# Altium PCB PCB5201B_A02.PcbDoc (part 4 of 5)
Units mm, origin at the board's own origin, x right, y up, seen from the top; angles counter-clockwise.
Board outline 115 x 60 mm, 6 copper layers (Top Layer, GND Layer 2, Signal Layer 3, Signal Layer 4, VCC Layer 5, Bottom Layer), stack 1.555 mm thick; 355 components, 250 nets, 1223 pads, 1070 vias.
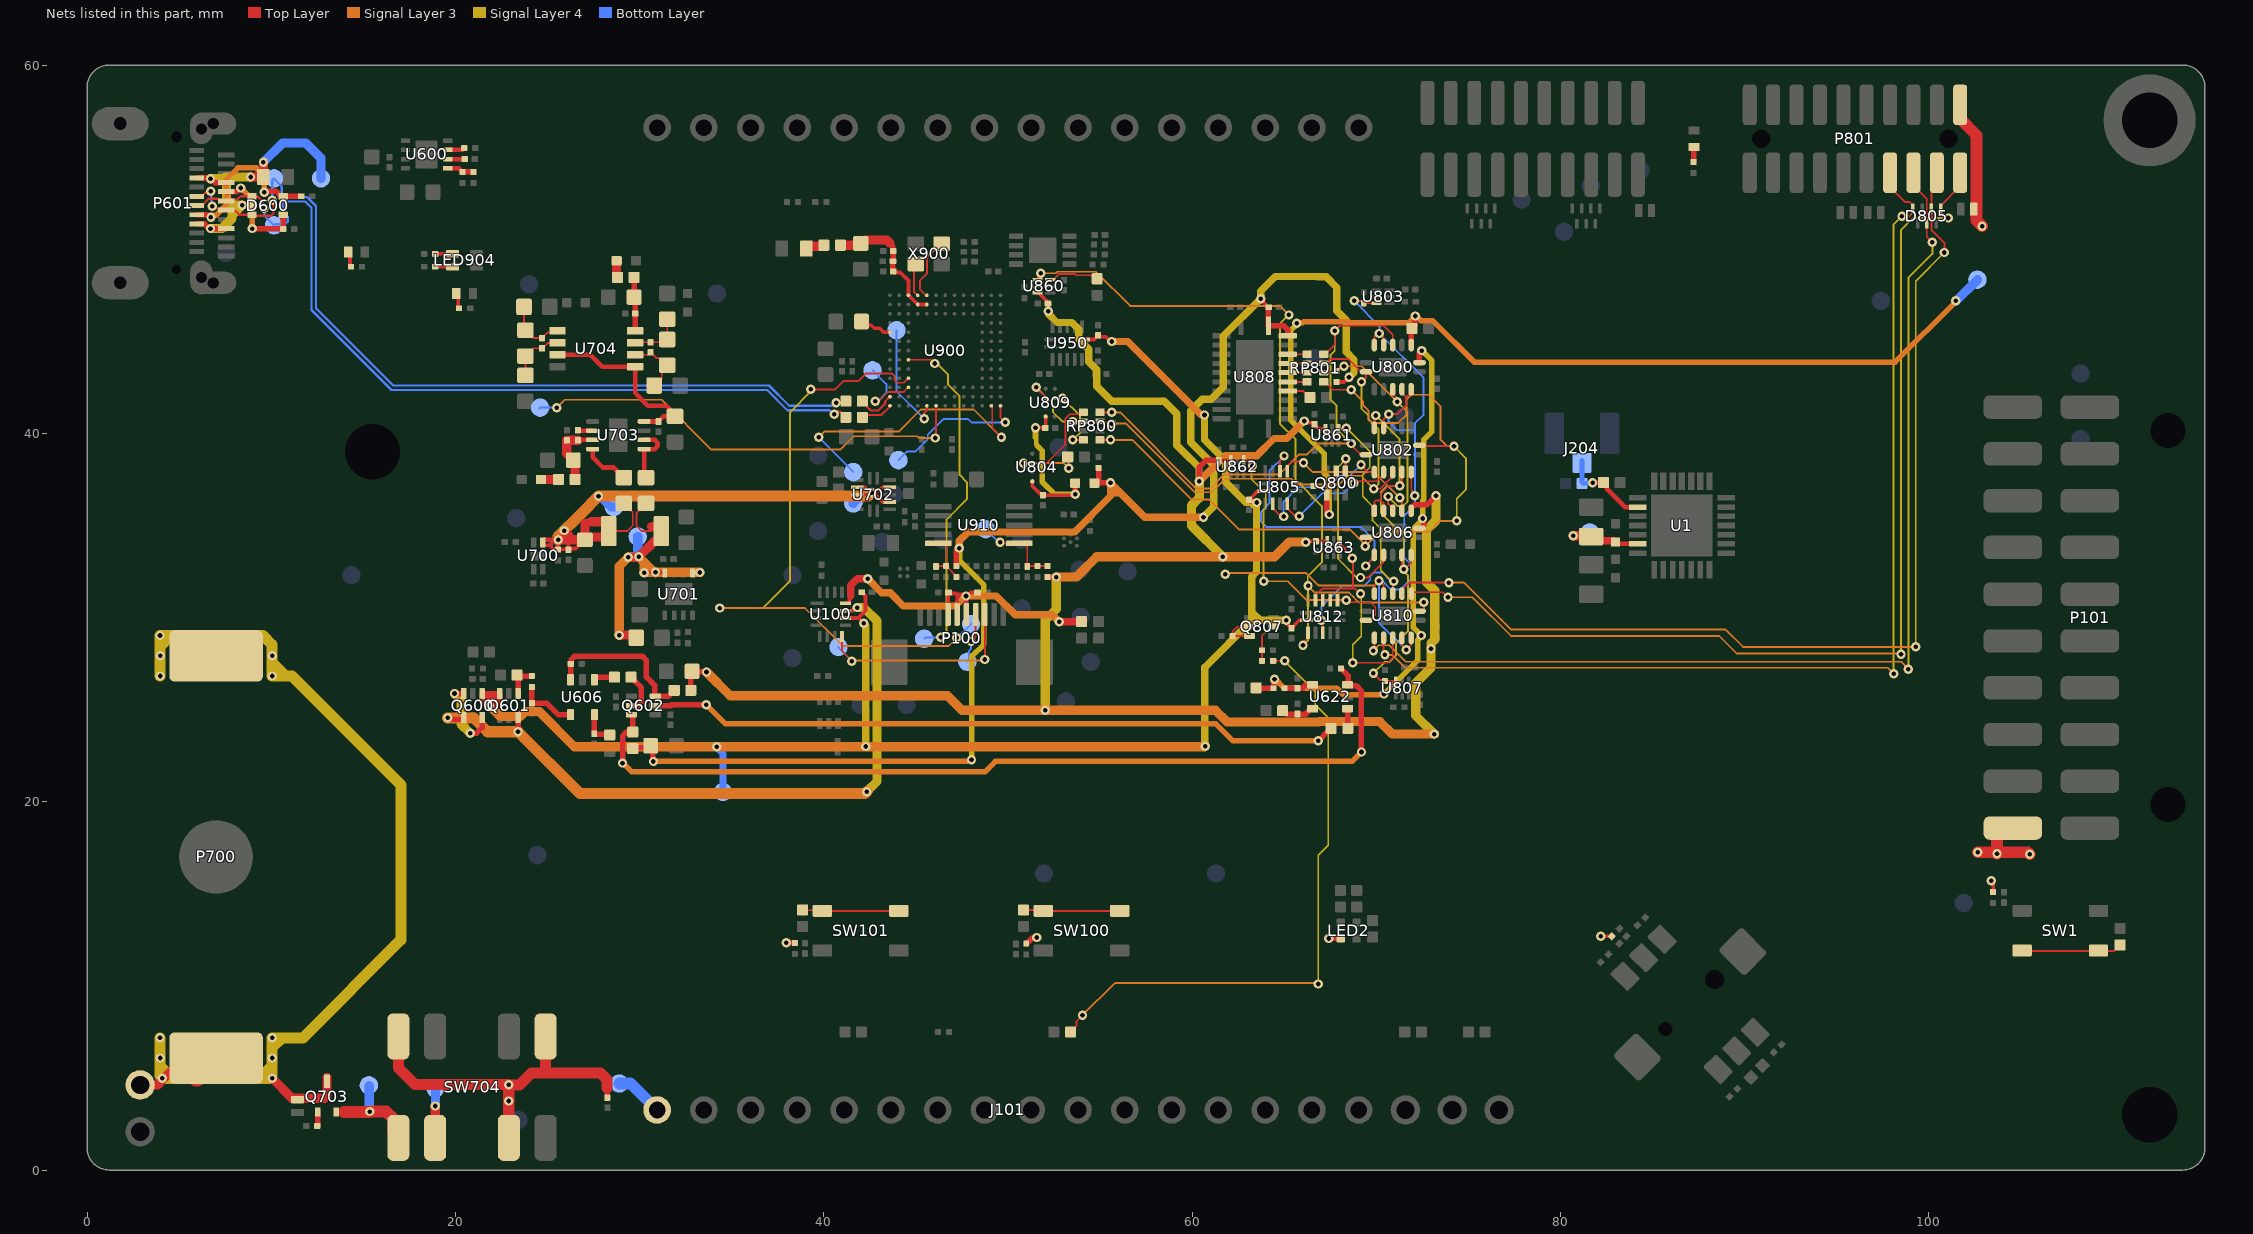
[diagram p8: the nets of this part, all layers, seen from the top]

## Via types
v1: diameter 0.508, hole 0.25, Top Layer to Bottom Layer, tented both sides, 1070 vias

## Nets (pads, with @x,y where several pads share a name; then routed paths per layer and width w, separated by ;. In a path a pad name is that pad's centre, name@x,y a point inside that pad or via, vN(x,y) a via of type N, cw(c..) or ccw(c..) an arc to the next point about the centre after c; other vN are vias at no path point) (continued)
N17208311: P100.8 TP152.1 U100.8 | length 12.3
  Top Layer w0.1: U100.8@40.99,28.975 40.99,28.21 41.531,27.669 v1(41.531,27.63) ; v1(48.75,27.725) P100.8@48.75,30.175
  Signal Layer 3 w0.1: v1(41.531,27.63) 41.576,27.675 v1@48.75,27.675
  Bottom Layer w0.1: TP152.1@40.8,28.4 40.8,28.38 41.531,27.65 v1(41.531,27.63)
N17208347: P100.7 TP153.1 | length 2.8
  Top Layer w0.1: v1(48,28.7) 48.25,28.95 P100.7@48.25,30.175
  Bottom Layer w0.1: TP153.1@47.8,27.6 47.891,27.691 47.891,28.191 48,28.3 v1(48,28.7)
N17209732: R104.1 SW100.1 SW100.2 | length 5.2
  Top Layer w0.1: R104.1@50.847,14.12 51.88,14.12 SW100.1@51.925,14.075 52.193,14.075 SW100.2@56.075,14.075
N17209791: R105.1 SW101.1 SW101.2 | length 5.4
  Top Layer w0.1: R105.1@38.8,14.175 38.865,14.11 39.89,14.11 SW101.1@39.925,14.075 ; SW101.1@39.9,14.05 SW101.1@39.925,14.075 ; SW101.2@44.075,14.075 SW101.1@39.925,14.075
N17247543: R7.2 SW1.3 SW1.4 | length 5.7
  Top Layer w0.1: SW1.3@104.848,11.9 110.075,11.9 R7.2@110.4,12.225
N17481376: D703.1 P700.1 Q703.3 ST701.2 | length 63.3
  Top Layer w0.5: ST701.2@2.875,4.62 3.82,4.62 v1@4.087,4.887 ; v1(4.087,4.981) v1@4.087,4.887 ; P700.1@7,6.078 5.278,6.078 v1@4.087,4.887 ; v1(10.046,4.981) 11.127,3.9 12.886,3.9 13.025,4.039 Q703.3@13.025,5.025
  Top Layer w1: P700.1@5.947,5.025 P700.1@7,6.078
  Signal Layer 4 w0.6: v1@3.95,27.9 v1@3.962,27.912 ; v1(3.958,7.181) 3.958,5.649 ; v1(3.962,26.825) v1@3.962,27.912 ; 3.975,5.666 3.958,5.649 ; 9.15,4.975 9.371,4.975 9.377,4.981 ; 10.05,6.65 10.581,7.181 ; 10.05,27.6 10.05,27.55 10.775,26.825 ; 3.958,5.649 4.625,4.981 ; 3.958,5.649 3.958,5.11 v1(4.087,4.981) 4.625,4.981 ; v1@3.962,27.912 v1(3.962,27.925) 3.962,28.437 ; 3.962,28.437 4.55,29.025 ; 3.962,28.437 3.962,29.019 3.958,29.023 v1(3.958,29.025) 4.55,29.025 ; 4.55,29.025 9.546,29.025 10.046,28.525 v1(10.046,27.925) v1(10.046,26.825) 10.775,26.825 ; 4.625,4.981 9.377,4.981 ; 9.377,4.981 10.046,5.65 ; 9.377,4.981 v1(10.046,4.981) 10.046,5.65 ; 10.046,5.65 v1(10.046,6.081) v1(10.046,7.181) 10.581,7.181 ; 10.581,7.181 11.714,7.181 17.039,12.506 17.039,20.919 11.133,26.825 10.775,26.825
  other v1: 3.962,6.081
N17481477: Q703.1 R792.2 | length 0.8
  Top Layer w0.3: R792.2@12.5,2.4 12.51,2.4 12.52,2.41 12.52,2.45 12.525,2.455 Q703.1@12.525,3.15
N17490696: C729.1 R718.2 U703.4 U704.3 U704.5 | length 10.5
  Top Layer w0.25: U704.3@25.545,44.275 27.325,44.275 27.975,43.625 U704.5@29.756,43.625 29.756,42.194 30.45,41.5 31.454,41.5 31.6,41.354 31.6,41.225 31.9,40.925 R718.2@31.925,40.925 31.3,40.925 C729.1@31.025,40.65 U703.4@30.25,40.65
N17490733: C766.2 R764.1 R765.2 U704.1 | length 3.4
  Top Layer w0.1: R764.1@23.725,46.875 23.725,45.675 R765.2@23.8,45.6 24.225,45.175 C766.2@24.7,45.175 24.7,45.195 24.81,45.305 24.83,45.305 25.009,45.484 25.453,45.484 U704.1@25.545,45.575
N17490783: C766.1 R765.1 R767.2 U704.2 | length 3.1
  Top Layer w0.1: R767.2@23.8,43.15 R765.1@23.8,44.2 24.225,44.625 C766.1@24.7,44.625 24.7,44.645 24.81,44.755 24.859,44.755 25.009,44.905 25.524,44.905 U704.2@25.545,44.925
N17490812: R709.1 U703.1 U703.2 | length 3.4
  Top Layer w0.25: U703.1@30.25,39.15 30.25,37.7 R709.1@30.35,37.6 R709.1@30.375,37.6 ; U703.2@30.25,39.65 30.825,39.65 30.971,39.504 30.971,39.296 30.825,39.15 U703.1@30.275,39.15
N17490814: R710.1 U703.8 | length 2.6
  Top Layer w0.25: U703.8@27.45,39.15 27.45,38.7 28,38.15 28.6,38.15 28.825,37.925 28.825,37.9 29.125,37.6 R710.1@29.15,37.6
N17490860: C710.2 U703.6 | length 0.8
  Top Layer w0.25: C710.2@26.65,40.175 26.675,40.15 U703.6@27.45,40.15
N17490888: L700.2 R717.1 | length 1
  Top Layer w0.5: L700.2@24.65,37.5 R717.1@25.6,37.5
N17491034: C770.2 R768.1 R769.2 U704.7 | length 2.7
  Top Layer w0.1: U704.7@29.756,44.925 29.781,44.95 C770.2@30.6,44.95 R769.2@31.35,44.95 ; R769.2@31.5,45.1 R768.1@31.5,46.2
N17491060: C770.1 R769.1 R771.2 U704.6 | length 3.5
  Top Layer w0.1: U704.6@29.756,44.275 30.475,44.275 C770.1@30.6,44.4 30.9,44.1 31.1,44.1 R769.1@31.5,43.7 31.2,43.4 31.2,43 R771.2@30.8,42.6
N17491108: L704.2 R731.2 | length 0.9
  Top Layer w0.5: L704.2@28.757,49.375 28.75,49.375 28.75,48.525 R731.2@28.8,48.475
N17491110: C730.1 C731.1 R731.1 U704.8 | length 2.9
  Top Layer w0.3: R731.1@29.7,48.475 C731.1@29.7,47.4 29.775,47.325 29.775,46.512 C730.1@29.772,46.509 29.764,46.501 29.764,45.583 U704.8@29.756,45.575
N17517174: RP801.5 U808.21 | length 1.1
  Top Layer w0.1: U808.21@65.195,44.3 RP801.5@66.25,44.3
N17517201: RP801.6 U808.20 | length 1.1
  Top Layer w0.1: U808.20@65.195,43.8 RP801.6@66.25,43.8
N17517230: RP801.7 U808.19 | length 1.1
  Top Layer w0.1: U808.19@65.195,43.3 RP801.7@66.25,43.3
N17517259: RP801.8 U808.18 | length 1.1
  Top Layer w0.1: U808.18@65.195,42.8 RP801.8@66.25,42.8
N17517278: R805.1 U808.17 | length 1.3
  Top Layer w0.1: U808.17@65.195,42.3 66.05,42.3 R805.1@66.4,41.95
N17517488: U802.9 U805.2 | length 7.7
  Top Layer w0.1: U805.2@64.375,36.185 64.375,35.945 v1@64.795,35.525 ; v1@69,38.3 v1(69.175,38.3) 69.575,37.9 U802.9@69.9,37.9
  Bottom Layer w0.1: v1(64.975,35.491) 64.975,36.3 65.75,37.075 67.375,37.075 68,37.7 68.575,37.7 v1(69.175,38.3)
N17517496: U802.10 U805.4 | length 6.7
  Top Layer w0.1: U805.4@65.175,36.185 65.175,35.925 65.6,35.5 v1(65.825,35.5) ; v1(68.775,37.3) 68.875,37.4 69.776,37.4 70.024,37.4 70.4,37.776 U802.10@70.4,37.9
  Bottom Layer w0.1: v1(65.825,35.5) 67.075,36.75 68.225,36.75 v1(68.775,37.3)
N17517567: R808.1 U802.6 U802.12 U806.5 U806.6 U806.12 U806.13 U807.3 | length 24.6
  Top Layer w0.1: v1(69.85,26.975) 70.224,26.601 70.424,26.601 R808.1@70.475,26.55 ; U806.6@69.9,35.8 69.9,36.275 69.975,36.35 70.25,36.35 ; U802.6@69.9,40.3 69.912,40.312 69.912,40.912 v1(69.975,40.975) ; U806.5@70.4,35.8 70.4,36.2 70.25,36.35 ; R808.1@70.475,26.525 70.5,26.55 71.038,26.55 U807.3@71.063,26.525 ; U806.12@71.4,33.4 71.4,32.835 71.5,32.735 v1(71.5,32.625) ; U802.12@71.4,37.9 71.4,37.275 v1(71.275,37.15) 70.669,37.15 70.25,36.731 70.25,36.35 ; v1@71.5,32.575 71.9,32.975 U806.13@71.9,33.4
  Signal Layer 4 w0.1: v1@69.85,27.025 69.9,27.025 70.457,27.582 70.707,27.582 71.075,27.95 71.075,28.6 71.725,29.25 71.725,32.29 71.5,32.515 v1(71.5,32.625) 71.5,34.45 70.25,35.7 70.25,36.8 70.6,37.15 v1(71.275,37.15) 71.275,39.675 v1(69.975,40.975)
N17517613: RP800.5 U804.C1 | length 4.2
  Top Layer w0.1: U804.C1@51.825,38.4 52.125,38.4 53.125,39.4 53.125,40.8 53.132,40.807 53.132,40.813 53.362,41.043 53.993,41.043 RP800.5@54.1,41.15
N17517626: RP800.6 U809.C2 | length 4.4
  Top Layer w0.1: v1(51.546,42.505) 51.546,42.464 52.05,41.96 U809.C2@52.05,41.925 ; v1(53.525,40.65) RP800.6@54.1,40.65
  Signal Layer 4 w0.1: v1(51.546,42.505) 52.45,41.601 52.45,41.15 52.95,40.65 v1(53.525,40.65)
N17517692: RP800.8 U809.C1 | length 3.8
  Top Layer w0.1: U809.C1@52.55,41.925 52.555,41.92 52.958,41.92 v1(52.964,41.914) ; v1(53.525,39.65) RP800.8@54.1,39.65
  Signal Layer 4 w0.1: v1(52.964,41.914) 53.918,40.96 53.918,40.043 v1(53.525,39.65)
N17517773: U805.9 U806.3 | length 8.1
  Top Layer w0.1: U805.9@65.175,37.955 65.175,38.25 65.4,38.475 65.975,38.475 v1(66.05,38.4) ; v1(71.275,36.5) 71.4,36.375 U806.3@71.4,35.8
  Signal Layer 3 w0.1: v1(66.05,38.4) 66.55,37.9 69.881,37.9 71.275,36.506 v1(71.275,36.5)
N17517791: U805.10 U806.9 | length 14
  Top Layer w0.1: U805.10@64.775,37.955 64.775,38.55 64.997,38.772 v1(64.997,38.778) ; v1(69.425,32.8) 69.9,33.275 U806.9@69.9,33.4
  Bottom Layer w0.1: v1(64.997,38.778) 64.997,38.772 64.2,37.975 64.2,36.2 63.75,35.75 63.75,35.2 64.025,34.925 69.15,34.925 69.9,34.175 69.9,33.275 v1(69.425,32.8)
N17517812: Q800.1 U806.10 | length 9.9
  Top Layer w0.1: Q800.1@68.325,37.95 68.334,37.959 68.334,38.609 v1(68.347,38.622) ; v1(69.15,32.175) 69.55,32.175 70.375,33 70.375,33.375 U806.10@70.4,33.4
  Signal Layer 4 w0.1: v1(68.347,38.622) 68.347,38.597 67.925,38.175 67.925,33.206 68.956,32.175 v1(69.15,32.175)
N17517960: R810.1 U804.C2 | length 3.7
  Top Layer w0.1: v1(50.85,38.388) 50.863,38.4 U804.C2@51.325,38.4 ; R810.1@53.25,38.725 53.3,38.675 v1(53.3,38.1)
  Signal Layer 3 w0.1: v1(50.85,38.388) 53.038,38.388 53.325,38.1 v1(53.3,38.1)
N17517966: Q800.2 R815.1 | length 1.7
  Top Layer w0.1: R815.1@66.59,37.142 67.192,37.142 67.825,37.775 Q800.2@67.825,37.95
N17518258: C804.1 C810.1 L801.2 U804.A2 U809.A2 | length 9.7
  Top Layer w0.2: U804.A2@51.325,37.4 51.325,37.15 51.825,36.65 C804.1@51.9,36.65 53.6,36.65 v1(53.65,36.7) ; v1(51.5,40.3) C810.1@52.025,40.3 52.05,40.325 U809.A2@52.05,40.925
  Top Layer w0.3: v1(53.65,36.7) L801.2@53.65,37.3
  Signal Layer 4 w0.25: 51.5,39.8 51.55,39.75 51.55,39.375 51.6,39.325
  Signal Layer 4 w0.3: 51.5,39.8 v1(51.5,40.3) ; 51.6,39.325 51.875,39.05 51.875,37.35 52.525,36.7 v1(53.65,36.7)
N17535327: U810.1 U812.1 U860.4 | length 42.6
  Top Layer w0.1: U860.4@51.6,48.35 U860.4@51.675,48.35 ; v1(66.025,28.5) 66.025,28.625 66.3,28.9 U812.1@66.3,29.165 ; U810.1@72.35,30.35 72.375,30.375 72.55,30.375 72.6,30.425 72.599,30.808 v1(72.582,30.825)
  Top Layer w0.2: U860.4@51.675,48.35 U860.4@51.725,48.4
  Top Layer w0.3: U860.4@51.725,48.4 51.725,48.582 51.794,48.651 v1(51.794,48.707)
  Signal Layer 3 w0.1: v1(51.794,48.707) 51.805,48.696 52.588,48.696 52.674,48.782 54.78,48.782 56.637,46.925 64.775,46.925 65.262,46.438 v1(65.262,46.434) ; v1(66.3,31.725) 66.668,31.357 68.524,31.357 68.807,31.074 68.807,31.062 69.037,30.832 69.049,30.832 69.056,30.825 v1(72.582,30.825)
  Signal Layer 4 w0.1: v1(65.262,46.434) 64.775,45.947 64.775,40.525 65.625,39.675 65.625,37.475 67.05,36.05 67.05,33 66.287,32.237 66.287,31.738 v1(66.3,31.725) 66.3,28.775 v1(66.025,28.5)
N17535335: R882.1 U860.3 | length 2.8
  Top Layer w0.1: U860.3@52.3,48.35 52.45,48.35 52.755,48.655 53.65,48.655 53.715,48.59 54.66,48.59 R882.1@54.85,48.4
N17535359: U810.4 U812.3 U861.4 | length 17.4
  Top Layer w0.1: v1(67.025,29.85) 67.1,29.775 U812.3@67.1,29.165 ; U861.4@67.95,40.25 68.425,40.25 v1@68.45,40.275 ; U810.4@70.9,31.3 70.9,31.875 70.95,31.925 v1(70.95,31.975)
  Signal Layer 4 w0.1: v1(68.375,40.275) 68.4,40.275 69.65,39.025 69.65,38.15 69.268,37.768 69.268,36.582 69.8,36.05 69.8,35.275 70.25,34.825 70.25,32.575 70.85,31.975 v1(70.95,31.975)
  Bottom Layer w0.1: v1(67.025,29.85) 67.025,30.6 68.15,31.725 69.35,31.725 69.675,32.05 69.675,32.25 69.875,32.45 70.325,32.45 70.8,31.975 v1(70.95,31.975)
N17535385: U810.8 U812.8 U862.4 | length 15.5
  Top Layer w0.1: U862.4@62.8,38.55 62.833,38.55 62.85,38.533 62.998,38.533 v1(63.283,38.248) ; U812.8@67.9,30.935 68.36,30.935 v1(68.375,30.95) 68.493,30.832 69.693,30.832 69.95,30.575 69.95,30.125 69.675,29.85 U810.8@69.45,29.85
  Signal Layer 3 w0.1: v1(63.9,31.975) 65.2,31.975 66.225,30.95 v1(68.375,30.95)
  Signal Layer 4 w0.1: v1(63.283,38.248) 63.225,38.189 63.225,37.525 64,36.75 64,35.95 63.875,35.825 v1@63.875,31.975
N17535407: U810.11 U812.11 U863.4 | length 13.2
  Top Layer w0.1: U812.11@66.7,30.935 66.7,31.2 67.075,31.575 68.743,31.575 ; U863.4@68.05,34.15 68.05,34.025 68.3,33.775 68.3,33.7 68.7,33.3 v1(68.7,33.225) 68.743,33.182 68.743,31.575 ; v1@68.723,27.55 70.625,27.55 70.9,27.825 U810.11@70.9,28.9 ; v1(69.15,31.3) 69.125,31.3 68.85,31.575 68.743,31.575
  Signal Layer 4 w0.1: v1(68.725,27.55) 68.725,28.525 69.193,28.993 69.193,31.218 69.15,31.261 v1(69.15,31.3)
N17535812: Q807.5 Q807.6 R838.1 | length 2.2
  Top Layer w0.1: Q807.6@63.125,29 63.123,28.998 62.203,28.998 R838.1@62.201,28.996 62.201,29.251 62.45,29.5 Q807.5@63.125,29.5
N17535874: Q807.2 R839.2 R841.1 | length 2.2
  Top Layer w0.1: R841.1@63.804,27.652 63.802,27.654 R839.2@63.8,28.225 R839.2@63.8,28.225 63.8,29.025 64.275,29.5 Q807.2@64.425,29.5
N17542071: R601.1 R602.2 U600.5 | length 1.5
  Top Layer w0.25: U600.5@19.582,54.397 20.182,54.397 R601.1@20.382,54.197
  Top Layer w0.3: R601.1@20.382,54.197 R602.2@20.982,54.197
N17542108: R600.1 U600.7 | length 0.9
  Top Layer w0.25: U600.7@19.582,55.397 20.382,55.397 R600.1@20.482,55.497
N17542152: C602.1 U600.6 | length 0.9
  Top Layer w0.25: U600.6@19.582,54.897 C602.1@20.507,54.897
N17542390: Q602.6 R674.1 R675.1 U606.3 | length 8.6
  Top Layer w0.3: U606.3@26.25,26.625 26.255,26.63 26.255,27.485 R674.1@26.26,27.49 26.27,27.49 26.28,27.5 26.28,27.707 26.474,27.9 30.15,27.9 30.375,27.675 30.375,26.773 30.825,26.323 Q602.6@30.825,25.8 ; Q602.6@30.85,25.725 31.557,25.725 R675.1@31.882,26.05
N17542428: Q602.2 R679.2 | length 2.2
  Top Layer w0.3: R679.2@29.535,26.761 30.1,26.196 30.1,25.426 29.899,25.225 Q602.2@29.55,25.225
N17542505: Q601.4 R628.1 R672.2 | length 1.8
  Top Layer w0.3: R628.1@23.35,26.875 R628.1@23.4,26.825 ; Q601.4@23.4,25.875 R628.1@23.4,26.825 ; R672.2@24.15,26.825 R628.1@23.4,26.825
N17542511: C621.1 R672.1 U606.4 | length 3.4
  Top Layer w0.3: R672.1@24.15,26.225 C621.1@24.15,25.35 24.95,25.35 25.575,24.725 U606.4@26.25,24.725 U606.4@26.25,24.85
N17542554: R679.1 U606.1 | length 1.2
  Top Layer w0.3: U606.1@27.55,26.625 27.55,26.711 27.6,26.761 R679.1@28.635,26.761
N17542610: C660.1 R681.1 U606.5 | length 1.9
  Top Layer w0.3: U606.5@27.575,24.675 27.544,24.644 27.544,23.691 C660.1@27.537,23.685 27.537,23.665 27.547,23.655 28.38,23.655 R681.1@28.425,23.7
N17542702: Q600.3 Q600.6 | length 4.3
  Top Layer w0.3: v1(19.95,25.875) Q600.6@20.45,25.875 ; v1(20.8,23.725) 21.15,23.725 21.45,24.025 Q600.3@21.45,24.575
  Signal Layer 4 w0.5: v1(19.95,25.875) 20.3,25.525 20.3,24.225 v1(20.8,23.725)
N17542835: Q602.3 R687.1 R688.1 U622.3 | length 49.2
  Top Layer w0.3: v1(29.075,22.1) 29.075,23.574 29.276,23.775 29.622,23.775 R687.1@29.629,23.783 ; Q602.3@29.55,24.725 29.625,24.725 R687.1@29.625,23.875 ; R688.1@68.086,27.233 68.096,27.233 68.475,26.854 U622.3@68.475,26.35 ; U622.3@68.375,26.375 68.441,26.309 68.916,26.309 69.2,26.025 v1(69.2,22.7)
  Signal Layer 3 w0.3: v1(29.075,22.1) 29.1,22.1 29.577,21.623 48.748,21.623 49.318,22.193 65.807,22.193 68.693,22.193 v1(69.2,22.7)
N17542861: Q602.5 R686.2 | length 37.8
  Top Layer w0.3: Q602.5@30.85,25.225 31.698,25.225 31.743,25.27 v1(33.618,25.27) ; v1(66.857,23.302) 67.39,23.834 67.408,23.834 67.5,23.926 R686.2@67.5,24.025
  Signal Layer 3 w0.3: v1(33.618,25.27) 34.663,24.225 61.3,24.225 62.223,23.302 v1(66.857,23.302)
N17542916: C653.1 R629.1 U622.4 | length 1.8
  Top Layer w0.1: U622.4@66.55,26.35 U622.4@66.65,26.35
  Top Layer w0.3: R629.1@65.019,26.163 65.663,26.163 C653.1@65.7,26.2 ; C653.1@65.675,26.15 65.7,26.175 66,26.175 66.125,26.3 66.5,26.3 U622.4@66.55,26.35
N17542947: R686.1 U622.1 | length 1
  Top Layer w0.3: U622.1@68.45,25.05 68.454,25.046 68.454,24.071 R686.1@68.475,24.05
N17542995: C652.1 R690.1 U622.5 | length 1.8
  Top Layer w0.3: R690.1@64.921,24.944 65.104,24.761 66.17,24.761 66.3,24.891 66.3,24.9 66.45,25.05 U622.5@66.55,25.05
N17547129: TPJ909.1 U900.C11 | length 4.5
  Top Layer w0.1: v1(42.8,41.75) 42.873,41.677 42.902,41.677 43.475,42.25 44.35,42.25 U900.C11@44.6,42.5
  Bottom Layer w0.1: TPJ909.1@42.651,43.427 43.4,42.679 43.4,42.2 42.95,41.75 v1(42.8,41.75) v1@42.8,41.7
N17547147: TPJ910.1 U900.D11 | length 36.4
  Top Layer w0.1: v1(39.304,42.392) 39.314,42.382 40.602,42.382 41.062,42.843 41.868,42.843 42.275,43.25 43.714,43.25 43.85,43.114 43.85,42.886 43.986,42.75 44.35,42.75 U900.D11@44.6,43
  Signal Layer 3 w0.1: v1(34.357,30.517) 38.983,30.517 41.05,28.45 46.775,28.45 v1(47.225,28.9)
  Signal Layer 4 w0.1: v1(34.357,30.517) 36.692,30.517 38.175,32 38.175,41.161 39.304,42.29 v1(39.304,42.392)
  Bottom Layer w0.1: v1(47.225,28.9) 47.253,28.9 TPJ910.1@48.003,29.65
N17547174: TPJ911.1 U900.F11 | length 18.7
  Top Layer w0.1: U900.F11@44.6,44 45.825,44 v1(46.025,43.8)
  Signal Layer 4 w0.1: v1(46.025,43.8) 46.125,43.8 46.75,43.175 46.75,42.65 47.375,42.025 47.375,37.75 47.775,37.35 47.775,36.425 46.675,35.325 46.675,29.25 v1(46.35,28.925)
  Bottom Layer w0.1: TPJ911.1@45.453,28.85 45.528,28.925 v1(46.35,28.925)
N17547291: TPJ900.1 U900.A2 | length 15.8
  Top Layer w0.1: U900.A2@49.1,41.5 49.1,41.473 49.15,41.423 49.15,40.3 v1(49.65,39.8)
  Signal Layer 3 w0.1: v1(39.725,39.8) 40.025,40.1 44.075,40.1 45.275,41.3 48.15,41.3 v1(49.65,39.8)
  Bottom Layer w0.1: v1(39.725,39.8) 41.602,37.923 TPJ900.1@41.602,37.9
N17547297: TPJ901.1 U900.A1 | length 7.9
  Top Layer w0.1: U900.A1@49.6,41.5 49.6,40.85 v1(49.85,40.6)
  Bottom Layer w0.1: TPJ901.1@44.053,38.55 44.528,39.025 45,39.025 45.65,39.675 45.65,39.925 46.5,40.775 47.85,40.775 48.025,40.6 v1(49.85,40.6)
N17547385: TPJ908.1 U900.A9 | length 6.2
  Top Layer w0.1: v1(45.45,40.8) 45.45,41.1 45.6,41.25 U900.A9@45.6,41.5
  Bottom Layer w0.1: TPJ908.1@43.952,45.601 43.952,42.298 v1(45.45,40.8)
N17547395: TPJ902.1 U900.A8 | length 24.9
  Top Layer w0.1: v1(46.05,39.75) 46.1,39.8 U900.A8@46.1,41.5
  Signal Layer 3 w0.1: v1(25.5,41.4) 25.925,41.825 31.2,41.825 33.9,39.125 40.9,39.125 41.625,39.85 45.075,39.85 45.175,39.75 v1(46.05,39.75)
  Bottom Layer w0.1: TPJ902.1@24.551,41.351 TPJ902.1@24.6,41.4 v1(25.5,41.4)
N17547487: R902.2 U900.B13 | length 2.1
  Top Layer w0.12: R902.2@42.1,41.75 42.34,41.51 42.34,41.461 42.561,41.24 42.959,41.24 43.34,41.621 43.34,41.74 U900.B13@43.6,42
N17547515: R904.2 U900.A13 | length 1.8
  Top Layer w0.12: R904.2@42.1,40.875 42.225,41 43.128,41 43.585,41.456 43.585,41.485 U900.A13@43.6,41.5
N17547530: U900.N9 X900.3 | length 3.5
  Top Layer w0.1: U900.N9@45.6,47.5 45.55,47.5 45.225,47.825 45.225,48.3 45.6,48.675 45.6,49.55 46.35,50.3 X900.3@46.4,50.3
N17547541: U900.N10 X900.1 | length 1.7
  Top Layer w0.1: X900.1@45,49.1 44.9,49 44.9,47.7 U900.N10@45.1,47.5
N17547732: LED903.2 R912.2 | length 0.9
  Top Layer w0.2: LED903.2@20.05,47.6 20.15,47.5 20.15,46.85 R912.2@20.2,46.8
N17547880: C900.1 U900.J13 | length 1.7
  Top Layer w0.2: C900.1@42.05,45.975 42.15,45.875 42.575,45.875 42.743,45.707 43.039,45.707 43.246,45.5 U900.J13@43.6,45.5
N17548050: C903.1 C904.1 C905.1 C906.1 R130.2 U900.M9 U900.M10 U900.N11 | length 7.6
  Top Layer w0.2: C904.1@43.77,48.802 43.83,48.742 44.158,48.742 44.6,48.3 U900.N11@44.6,47.5 U900.M10@45.1,47 U900.M9@45.6,47
  Top Layer w0.3: 43.35,50.5 43.396,50.5 ; 43.573,50.323 43.75,50.146 43.75,49.906 43.76,49.896 C906.1@43.773,49.896 43.773,49.362 43.763,49.352 C905.1@43.76,49.352 43.76,48.812 43.77,48.802 C904.1@43.773,48.802
  Top Layer w0.5: R130.2@40.904,50.219 41.91,50.219 C903.1@42.006,50.315 ; C903.1@41.968,50.268 C903.1@42.075,50.375 ; C903.1@42.1,50.4 42.2,50.5 43.35,50.5 ; 43.396,50.5 43.43,50.5 43.59,50.34
N17548152: L900.2 R130.1 | length 0.9
  Top Layer w0.5: L900.2@39.166,50.043 39.292,50.169 39.954,50.169 R130.1@40.004,50.219
N17559567: LED904.2 R920.2 | length 0.9
  Top Layer w0.2: R920.2@18.9,49.75 LED904.2@19.85,49.75
N17559569: LED904.1 R919.2 | length 0.9
  Top Layer w0.2: R919.2@18.9,49.05 LED904.1@19.85,49.05
N17559571: LED900.1 R900.2 | length 0.8
  Top Layer w0.3: R900.2@87.235,54.74 87.242,54.748 87.242,55.542 LED900.1@87.25,55.55
N17559573: LED901.1 R903.2 | length 0.9
  Top Layer w0.2: LED901.1@14.175,49.85 14.275,49.75 14.275,49.1 R903.2@14.325,49.05
N17564018: Q703.2 SW704.1 TP156.1 | length 5.8
  Top Layer w0.3: Q703.2@13.525,3.15 13.95,3.15
  Top Layer w0.635: 13.95,3.15 v1@15.325,3.15 ; v1(15.35,3.175) 16.246,3.175 16.618,2.803 16.618,2.033 SW704.1@16.9,1.75
  Bottom Layer w0.3: TP156.1@15.3,4.6 TP156.1@15.325,4.575 ; v1@15.325,3.2 v1(15.35,3.175)
  Bottom Layer w0.5: v1@15.325,3.2 TP156.1@15.325,4.575
N17564406: SW704.2 TP704.1 | length 2.6
  Top Layer w0.5: SW704.2@18.9,1.75 v1(18.9,3.475)
  Bottom Layer w0.5: TP704.1@18.91,4.43 18.925,4.415 v1@18.925,3.55
SI_HEADER_ENABLE: R807.1 U800.5 U800.6 U800.12 U800.13 U802.5 U802.13 U803.3 U810.5 U810.6 U810.12 U810.13 | length 45.4
  Top Layer w0.1: v1(68.8,47.2) 68.805,47.195 69.215,47.195 69.325,47.085 R807.1@69.325,47.075 U803.3@70.025,47.075 ; U810.6@69.9,31.3 69.9,31.75 v1(70.15,32) 70.4,31.75 U810.5@70.4,31.3 ; U800.6@69.9,44.8 69.9,45.25 70.075,45.425 v1(70.175,45.425) 70.4,45.2 U800.5@70.4,44.8 ; U802.5@70.4,40.3 70.4,40.775 v1(70.675,41.05) 71.15,41.05 71.625,41.525 71.625,41.975 ; U810.12@71.4,28.9 71.4,28.475 v1(71.625,28.25) 71.9,28.525 U810.13@71.9,28.9 ; U800.12@71.4,42.4 71.4,42.2 71.625,41.975 ; U800.13@71.875,42.45 U800.13@71.925,42.4 ; U802.13@71.9,37.9 71.9,36.935 72.075,36.76 v1@72.075,36.625 ; U800.13@71.9,42.4 71.9,42.25 71.625,41.975
  Signal Layer 3 w0.1: v1@61.85,32.425 66.175,32.425 66.85,31.75 69.9,31.75 v1(70.15,32)
  Bottom Layer w0.1: v1(68.8,47.2) 70.171,45.829 70.171,45.421 v1@70.1,45.35 ; v1(70.175,45.425) 72.575,43.025 72.575,41.025 72.1,40.55 72.1,40.175 ; v1(70.675,41.05) 70.675,40.65 71.15,40.175 72.1,40.175 ; v1(71.625,28.25) 70.15,29.725 v1(70.15,32) 70.325,32 70.8,31.525 71.3,31.525 71.893,32.118 71.893,32.882 71.525,33.25 71.525,35.525 72.1,36.1 v1(72.1,36.625) 72.1,40.175
  other v1: 61.8,32.35
SI_VCOM_CTS: D805.4 P801.8 U810.10 | length 57.6
  Top Layer w0.1: U810.10@70.4,28.9 70.4,28.05 v1(70.475,27.975) ; P801.8@97.905,54.158 97.905,53.37 98.7,52.575 98.96,52.575 99.15,52.385 99.15,52 98.95,51.8 v1(98.55,51.8)
  Signal Layer 3 w0.1: v1(70.475,27.975) 70.875,27.975 71.575,27.275 97.775,27.275 v1(98.1,26.95)
  Signal Layer 4 w0.1: v1(98.1,26.95) 98.1,47.425 98.1,51.35 v1(98.55,51.8)
SI_VCOM_RTS: D805.6 P801.6 U810.9 | length 58.4
  Top Layer w0.1: v1(69.85,28.2) 69.9,28.25 U810.9@69.9,28.9 ; P801.6@99.175,54.158 99.175,53.475 99.9,52.75 D805.6@99.9,51.385 99.9,50.675 v1(100.2,50.375)
  Signal Layer 3 w0.1: v1(69.85,28.2) 70.15,28.5 70.7,28.5 71.6,27.6 98.5,27.6 v1(98.9,27.2)
  Signal Layer 4 w0.1: v1(98.9,27.2) 98.9,48.45 100.2,49.75 v1(100.2,50.375)
SI_VCOM_RXD: D805.1 P801.2 U810.2 | length 57.1
  Top Layer w0.1: U810.2@71.9,31.3 71.9,31.375 73.625,31.375 v1(73.9,31.1) ; v1(101.075,51.7) 101,51.7 100.65,52.05 D805.1@100.65,52.215 100.65,52.375 101.715,53.44 P801.2@101.715,54.158
  Signal Layer 3 w0.1: v1(73.9,31.1) 75.225,31.1 77.325,29 88.619,29 89.569,28.05 98.464,28.05 v1(98.5,28.014)
  Signal Layer 4 w0.1: v1(98.5,28.014) 98.5,50.579 ; 98.499,50.579 98.499,50.905 98.5,51.05 99.15,51.7 v1(101.075,51.7)
SI_VCOM_TXD: D805.2 P801.4 U810.3 | length 56.5
  Top Layer w0.1: U810.3@71.4,31.3 71.4,31.5 71.8,31.9 v1(73.95,31.9) ; P801.4@100.445,54.158 100.15,53.863 D805.2@100.15,52.215 100.15,51.05 100.869,50.331 100.869,49.844 v1(100.85,49.825)
  Signal Layer 3 w0.1: v1(73.95,31.9) 74.775,31.9 77.325,29.35 88.975,29.35 89.918,28.407 v1(99.3,28.407)
  Signal Layer 4 w0.1: v1(99.3,28.407) 99.3,48.275 v1(100.85,49.825)
TCK_SWCLK: RP800.3 RP801.3 U800.8 U802.11 | length 28.5
  Top Layer w0.1: RP800.3@55,40.65 55.058,40.592 55.575,40.592 v1(55.633,40.534) ; RP801.3@67.15,43.8 67.289,43.8 67.539,44.05 68.475,44.05 69.175,43.35 U800.8@69.45,43.35 69.45,43.05 v1@69.203,42.803 ; v1(69.875,37) 70.224,37 70.9,37.676 U802.11@70.9,37.9
  Signal Layer 3 w0.1: v1(55.633,40.534) 56.427,40.534 60.154,36.807 61.068,36.807 61.799,37.538 65.387,37.538 65.7,37.225 67.975,37.225 68.45,37.7 69.175,37.7 v1(69.875,37)
  Signal Layer 4 w0.1: v1(69.203,42.802) 69.203,41.347 69.575,40.975 69.575,40.8 70.125,40.25 70.125,37.25 v1(69.875,37)
TDI: RP800.1 RP801.1 U802.1 U806.8 | length 40.9
  Top Layer w0.1: RP800.1@55,39.65 v1(55.575,39.65) ; RP801.1@67.15,42.8 67.227,42.8 67.652,42.375 v1(68.65,42.375) ; v1@69.45,33.975 U806.8@69.45,34.35 ; U802.1@72.35,39.35 72.374,39.326 74.202,39.326 v1(74.226,39.302)
  Signal Layer 3 w0.1: v1(55.575,39.65) 56.746,39.65 59.989,36.407 60.926,36.407 62.544,34.789 68.561,34.789 69.4,33.95 v1(69.4,33.875) 70.2,34.675 72.875,34.675 73.45,35.25 v1(74.375,35.25) ; v1(68.65,42.375) 69.275,41.75 69.275,41.55 69.575,41.25 69.575,40.75 69.75,40.575 71.2,40.575 71.65,41.025 71.65,41.85 71.9,42.1 72.85,42.1 73.5,41.45 73.5,39.65 73.822,39.328 74.147,39.328 v1@74.2,39.275
  Signal Layer 4 w0.1: v1(74.226,39.302) 74.875,38.653 74.875,36.95 74.375,36.45 v1(74.375,35.25)
TDO_SWO: R801.1 RP801.2 U800.11 U806.4 | length 13.7
  Top Layer w0.1: RP801.2@67.15,43.3 67.196,43.346 67.803,43.346 R801.1@67.849,43.393 67.849,43.403 68.018,43.572 68.172,43.572 v1@68.225,43.625 ; v1@68.175,43.625 v1@68.225,43.625 ; v1(68.25,43.65) v1@68.225,43.625 ; v1(70.65,36.575) 70.65,36.174 70.9,35.924 U806.4@70.9,35.8 ; U800.11@70.9,42.4 70.9,42.175 71.15,41.925 v1(71.15,41.725)
  Signal Layer 3 w0.1: v1(68.25,43.65) 69.225,43.65 v1(71.15,41.725)
  Signal Layer 4 w0.1: v1(70.65,36.575) 70.65,36.569 71.169,36.05 71.45,36.05 71.7,36.3 71.7,41.175 v1(71.15,41.725)
TMS_SWDIO: RP800.4 RP801.4 U800.4 U802.8 | length 29.9
  Top Layer w0.1: RP800.4@55,41.15 55.008,41.142 v1(55.646,41.142) ; RP801.4@67.15,44.3 67.225,44.3 67.75,44.825 v1(67.75,45.575) 68.025,45.85 70.4,45.85 70.9,45.35 U800.4@70.9,44.8 ; v1(68.65,39.45) 68.575,39.45 69.175,38.85 U802.8@69.45,38.85
  Signal Layer 3 w0.1: v1(55.646,41.142) 56.102,41.142 60.237,37.007 60.985,37.007 61.753,37.775 64.75,37.775 65.832,38.857 66.257,38.857 66.85,39.45 v1(68.65,39.45)
  Signal Layer 4 w0.1: v1(67.75,45.575) 67.75,44.5 67.525,44.275 67.525,41.825 67.85,41.5 67.85,40.225 68.625,39.45 v1(68.65,39.45)
UFL_ADC_IN: J204.1 R5.1 R220.2 U1.2 | length 5
  Top Layer w0.25: v1(81.75,37.325) R5.1@82.35,37.325 82.525,37.15 82.525,37 83.525,36 U1.2@84.325,36
  Bottom Layer w0.25: J204.1@81.175,38.55 81.175,37.35 81.225,37.3 81.725,37.3 v1(81.75,37.325)
USB_DM: D600.6 P601.A7 P601.B7 R902.1 TPJ612.1 | length 47
  Top Layer w0.12: P601.B7@5.95,52.875 6.215,52.875 6.409,53.069 6.639,53.069 v1(6.713,53.143) ; v1(6.788,52.337) 6.862,52.263 7.012,52.263 7.075,52.2 7.475,52.2 7.604,52.071 8.079,52.071 8.276,51.874 D600.6@8.947,51.874 8.998,51.822 9.997,51.822 10.115,51.94 10.115,52.595 v1(10.049,52.66) ; v1(40.669,41.657) 41.107,41.657 R902.1@41.2,41.75
  Bottom Layer w0.12: v1(6.713,53.143) 6.75,53.106 6.75,52.375 v1(6.788,52.337) ; v1@10.05,52.7 10.05,53.75 TPJ612.1@10.15,53.85 10.15,53.826 10.569,53.407 10.569,53.031 10.76,52.84 11.935,52.84 12.425,52.35 12.425,46.8 16.625,42.6 37.025,42.6 38.125,41.5 40.431,41.5 40.588,41.657 v1(40.669,41.657)
USB_DP: D600.4 P601.A6 P601.B6 R904.1 TPJ611.1 | length 46.4
  Top Layer w0.12: P601.B6@5.95,52.375 6.025,52.45 6.3,52.45 6.59,52.74 7.12,52.74 7.235,52.625 P601.A6@7.55,52.625 7.625,52.7 8.155,52.7 8.329,52.874 D600.4@8.947,52.874 8.97,52.85 9.275,52.85 9.576,52.549 9.576,52.274 v1(9.625,52.225) ; v1(40.578,41.047) 40.704,41.173 40.898,41.173 40.9,41.175 R904.1@41.2,40.875
  Bottom Layer w0.12: v1(9.625,52.225) 9.625,51.825 TPJ611.1@10.15,51.3 10.21,51.36 10.76,51.36 10.9,51.5 10.9,51.78 10.605,52.075 10.605,52.53 10.675,52.6 11.836,52.6 12.185,52.251 12.185,46.701 16.526,42.36 36.926,42.36 38.026,41.26 40.315,41.26 40.528,41.047 v1(40.578,41.047)
USBC_CC1: D600.1 P601.A5 R621.2 | length 5.9
  Top Layer w0.3: P601.A5@7.55,53.125 8.1,53.125 8.3,53.325 v1(8.35,53.325) ; v1(8.975,51.125) 8.99,51.11 10.64,51.11 R621.2@10.648,51.102 ; R621.2@10.65,51.1 R621.2@10.648,51.102 ; D600.1@10.675,51.875 10.648,51.848 R621.2@10.648,51.102
  Signal Layer 3 w0.3: v1(8.35,53.325) 8.975,52.7 v1(8.975,51.125) v1@8.975,51.05
USBC_CC2: D600.3 P601.B5 R620.2 | length 8.9
  Top Layer w0.3: P601.B5@5.95,51.875 6.525,51.875 6.667,51.733 v1(6.723,51.733) ; v1(9.625,53.1) 9.708,53.017 9.845,53.153 10.253,53.153 10.533,52.874 D600.3@10.647,52.874 11.599,52.874 R620.2@11.6,52.875
  Signal Layer 3 w0.3: v1(6.723,51.733) 6.779,51.733 6.891,51.844 6.992,51.844 7.55,52.403 7.55,53.786 8.182,54.418 9.173,54.418 9.625,53.965 v1(9.625,53.1)
USBC_VBUS: D600.5 L600.1 P601.A4 P601.A9 P601.B4 P601.B9 TPJ613.1 | length 18
  Top Layer w0.3: P601.B4@5.95,51.375 6.384,51.375 6.594,51.165 6.66,51.165 v1(6.7,51.125) ; P601.B9@5.95,53.875 6.475,53.875 6.485,53.865 6.66,53.865 v1(6.7,53.825) ; v1@6.675,53.825 v1(6.7,53.825) ; v1@6.725,51.125 P601.A9@7.55,51.125 ; P601.A4@7.55,53.625 6.956,53.625 6.756,53.825 v1(6.7,53.825) ; v1(8.425,52.4) 8.438,52.387 8.934,52.387 D600.5@8.947,52.374
  Top Layer w0.5: v1@8.876,53.926 L600.1@9.57,53.926 ; L600.1@9.57,53.926 9.573,53.93 v1(9.575,54.725) v1(9.575,54.725)
  Signal Layer 4 w0.5: v1(6.7,53.825) 7.382,53.825 ; v1@6.8,51.125 7.325,51.125 7.868,51.668 7.868,52.4 ; 7.868,51.843 v1(8.425,52.4) ; v1@8.35,52.4 7.868,52.4 ; v1(8.875,53.925) 7.868,53.925 ; 7.382,53.825 7.482,53.925 7.868,53.925 ; 7.382,53.825 7.575,53.632 ; 7.575,53.632 7.575,52.693 7.868,52.4 ; 7.575,53.632 7.868,53.925
  Bottom Layer w0.5: v1@9.6,54.75 10.625,55.775 11.875,55.775 12.7,54.95 TPJ613.1@12.7,53.85
V_SW: C104.1 C800.1 C828.1 C950.1 Q600.4 Q601.6 TPJ608.1 U100.10 U805.14 U812.14 U950.14 | length 91.9
  Top Layer w0.2: U100.10@41.19,29.975 41.9,29.975 v1(42.175,29.7) ; 41.87,29.975 42.27,30.376 42.27,31.127 42.243,31.154 42.243,31.197 42.153,31.287 42.153,31.314 42.093,31.374 C104.1@42.073,31.374 ; U950.14@54.11,45.1 54.675,45.1 54.82,45.245 54.84,45.245 54.9,45.305 C950.1@54.9,45.325 54.946,45.279 54.946,45.259 54.96,45.245 55.311,45.245 55.562,44.994 v1(55.646,44.994) ; v1(63.521,36.25) 63.55,36.25 63.525,36.275 63.225,36.275 C800.1@63.1,36.4 63.57,36.87 U805.14@63.89,36.87 ; v1(65.125,29.85) 65.125,29.7 C828.1@65.4,29.425 65.825,29.85 U812.14@66.215,29.85
  Top Layer w0.3: 21.45,25.475 22.282,25.475 22.341,25.416 ; 21.45,25.475 Q600.4@21.45,25.625 ; 21.45,25.475 21.7,25.225 v1(21.85,25.225) 22.15,25.225 22.341,25.416 ; Q600.4@21.45,25.625 Q601.6@22.4,25.625 ; Q600.4@21.45,25.625 Q600.4@21.45,25.875 Q601.6@22.4,25.875 Q601.6@22.4,25.625 ; 22.341,25.416 22.4,25.475 Q601.6@22.4,25.625
  Signal Layer 3 w0.4: v1(55.646,44.994) 56.506,44.994 60.5,41 v1(60.675,41)
  Signal Layer 3 w0.5: v1(21.85,25.225) 22.45,24.625 23.525,24.625 23.8,24.9 24.55,24.9 26.459,22.991 42.264,22.991 42.271,22.998 v1@42.272,22.997 ; v1@42.284,22.991 60.679,22.991 60.707,23.019 v1@60.708,23.018
  Signal Layer 4 w0.4: v1(42.175,29.7) 42.175,29.671 42.275,29.571 v1(42.275,23) ; v1(60.675,41) 60.675,39.65 61.825,38.5 61.825,37.35 62.925,36.25 63.225,36.25 ; v1(60.711,23.021) 60.7,23.032 60.7,27.3 63.25,29.85 ; 63.325,30.225 63.7,29.85 ; v1(65.125,29.85) 63.7,29.85 ; 63.225,36.25 63.373,36.25 v1(63.521,36.25) 63.5,36.229 63.5,35.975 ; 63.225,36.25 63.373,36.102 63.5,35.975 ; 63.25,29.85 63.25,30.225 63.25,32.225 63.5,32.475 63.5,35.975 ; 63.25,29.85 63.7,29.85
  Bottom Layer w0.4: v1(34.183,22.991) 34.183,22.962 34.528,22.616 TPJ608.1@34.528,20.527
VCOM_CTS: U812.9
VCOM_ENABLE: R304.1 R841.2 | length 34.1
  Top Layer w0.1: R304.1@53.4,7.5 53.725,7.825 53.725,8.075 v1(54.05,8.4) ; R841.2@64.404,27.652 65.027,27.652 v1(65.025,27.65)
  Signal Layer 3 w0.1: v1(54.05,8.4) 55.8,10.15 66.8,10.15 v1(66.85,10.1)
  Signal Layer 4 w0.1: v1(65.025,27.65) 65.361,27.314 65.363,27.314 66.693,25.984 66.693,25.255 67.4,24.548 67.4,17.64 66.85,17.09 v1(66.85,10.1)
VCOM_RTS: U812.10
VCS: C710.1 C714.1 C728.1 R717.2 U703.7 | length 3.7
  Top Layer w0.25: C710.1@26.675,39.65 U703.7@27.45,39.65
  Top Layer w0.3: C710.1@26.65,39.625 C710.1@26.675,39.65
  Top Layer w0.5: R717.2@26.5,37.5 26.5,38.45 C714.1@26.4,38.55 26.05,38.9 C728.1@26.05,39.625 C710.1@26.65,39.625
VDISP: C143.1 C144.1 P100.4 P100.5 P100.6 R145.2 U100.12 | length 20.6
  Top Layer w0.2: U100.12@41.19,30.775 41.39,30.775 41.39,30.975 ; 41.4,31.25 41.39,31.24 41.39,30.975 ; 41.45,31.1 41.45,31.035 41.39,30.975 ; P100.4@46.75,30.175 46.762,30.187 46.762,31.352 C143.1@46.774,31.364 46.834,31.304 47.196,31.304 47.25,31.25 ; P100.5@47.25,30.175 47.25,31.25 ; P100.6@47.75,30.175 v1@47.75,31.174 ; v1@47.75,31.175 47.725,31.2 v1@47.815,31.2 ; C144.1@48.35,31.368 47.984,31.368 v1@47.815,31.2 ; 47.25,31.25 47.575,31.25 47.65,31.174 v1(47.724,31.174) v1@47.75,31.174 ; v1@47.75,31.174 47.79,31.174 v1@47.815,31.2
  Top Layer w0.4: 41.475,31.175 41.475,31.75 41.825,32.1 v1(42.384,32.1) ; R145.2@54.007,29.782 R145.2@54.007,29.782 v1@52.784,29.781 ; v1(52.783,29.781) v1@52.784,29.781
  Signal Layer 3 w0.4: v1(42.384,32.1) 43.137,31.347 43.61,31.347 44.325,30.632 47.153,30.632 47.695,31.174 49.368,31.174 50.396,30.146 52.418,30.146 v1@52.763,29.801
VMCU: C1.1 C2.1 C706.1 D808.1 J101.1 LED2.1 P101.2 P801.1 Q600.1 Q601.3 R9.1 R100.2 R101.2 R111.2 SW704.3 SW704.5 SW704.8 TP157.1 TP703.1 U1.6 U100.11 | length 79.8
  Top Layer w0.2: U100.11@41.19,30.375 41.56,30.375 41.729,30.544 v1(41.812,30.544) ; v1(82.2,12.7) 82.212,12.688 R111.2@82.788,12.688 ; v1(103.4,15.7) 103.5,15.6 R9.1@103.5,15.1
  Top Layer w0.25: C2.1@83.05,34.075 83.125,34 U1.6@84.325,34
  Top Layer w0.3: v1(19.577,24.551) 19.577,24.548 19.65,24.475 20.35,24.475 Q600.1@20.45,24.575 ; v1(23.4,23.8) Q601.3@23.4,24.575 ; 28.24,4.45 28.24,3.935 C706.1@28.25,3.925 ; v1@37.9,12.325 37.917,12.342 38.421,12.342 R101.2@38.429,12.333 ; R100.2@51,12.3 51.025,12.3 51.35,12.625 v1(51.575,12.625) ; v1(67.425,12.575) LED2.1@68.075,12.575
  Top Layer w0.4: C1.1@81.675,34.4 81.9,34.175 82.925,34.175 C2.1@83,34.1
  Top Layer w0.5: v1(80.7,34.45) 80.702,34.448 81.508,34.448 C1.1@81.58,34.377
  Top Layer w0.6: SW704.5@16.9,7.25 16.9,5.55 17.8,4.65 v1@22.75,4.65 ; v1(22.9,4.625) 23.475,4.625 24.125,5.275 24.9,5.275 ; SW704.8@24.9,7.25 24.9,5.275 ; 28.24,4.45 28.24,4.924 27.889,5.275 24.9,5.275
  Top Layer w0.635: SW704.3@22.9,1.75 v1(22.9,3.75) v1(22.9,4.625) ; P801.1@101.715,57.841 101.715,57.085 102.6,56.2 ; 102.598,56.173 102.598,51.546 v1(102.9,51.244) ; v1(102.67,17.264) v1@103.709,17.264 ; v1(103.709,17.184) v1@103.709,17.264 ; P101.2@104.57,18.57 104.027,18.57 103.709,18.253 v1@103.709,17.264 ; v1(105.498,17.155) 105.389,17.264 v1@103.709,17.264
  Signal Layer 3 w0.6: v1(19.577,24.551) 20.999,24.551 21.75,23.8 v1(23.4,23.8) 26.758,20.442 42.232,20.442 v1(42.341,20.552)
  Signal Layer 4 w0.3: v1(19.577,24.551) v1@19.625,24.503
  Signal Layer 4 w0.5: v1(41.812,30.544) 41.814,30.542 42.171,30.542 42.9,29.813 42.9,21.112 42.341,20.554 v1(42.341,20.552)
  Bottom Layer w0.3: v1@80.692,34.471 80.778,34.471 80.797,34.491 81.466,34.491 TP157.1@81.6,34.625
  Bottom Layer w0.635: TP703.1@28.9,4.7 29.512,4.7 J101.1@30.95,3.262
  other v1: 37.968,12.35
VMCU_BUF: C625.1 C861.1 C863.1 C865.1 C867.1 R630.2 R675.2 U806.2 U860.6 U861.6 U862.6 U863.6 | length 114.4
  Top Layer w0.2: U860.6@51.6,47.65 51.65,47.65 52.175,47.125 C863.1@52.175,47.05 52.188,47.037 52.188,46.655 v1(52.201,46.642) ; C861.1@61.45,38.55 U862.6@62.1,38.55 ; v1(66.099,40.674) 66.182,40.674 66.275,40.58 66.59,40.58 66.65,40.52 66.65,40.48 66.88,40.25 U861.6@67.25,40.25 ; v1(66.175,34.1) 66.225,34.15 C867.1@66.725,34.15 U863.6@67.35,34.15
  Top Layer w0.3: R675.2@32.782,26.05 32.782,27.015 C625.1@32.848,27.08 32.866,27.063 33.618,27.063 v1(33.635,27.046) ; R630.2@52.15,32.2 v1(52.625,32.2) ; v1(60.4,37.4) 60.4,38.179 60.771,38.55 C861.1@61.45,38.55 ; U806.2@71.9,35.8 71.9,35.95 72.075,36.125 72.75,36.125 v1(73.25,36.625)
  Signal Layer 3 w0.4: v1(60.4,37.4) 61.79,38.79 63.515,38.79 64.452,39.727 65.152,39.727 v1(66.099,40.674)
  Signal Layer 3 w0.5: v1(33.635,27.046) 34.924,25.757 46.718,25.757 47.512,24.963 v1@52.013,24.963 ; v1(52.025,24.975) v1@52.013,24.963 ; v1(52.625,32.2) 53.729,32.2 54.829,33.3 v1(61.675,33.3) 64.475,33.3 65.275,34.1 v1(66.175,34.1) ; v1(73.15,23.675) 70.875,23.675 70.2,24.35 66.915,24.35 66.892,24.327 61.905,24.327 61.269,24.963 v1@52.013,24.963
  Signal Layer 4 w0.4: v1(52.201,46.642) 52.221,46.621 52.221,46.474 52.67,46.025 53.475,46.025 53.85,45.65 53.85,45.123 54.4,44.573 54.4,43.889 54.825,43.464 54.825,42.559 55.634,41.75 58.5,41.75 59.175,41.075 59.175,39.35 59.55,38.975 ; 59.559,38.984 60.379,38.163 60.379,37.421 v1(60.4,37.4)
  Signal Layer 4 w0.5: v1(52.025,24.975) 52.025,29.861 52.625,30.461 v1(52.625,32.2) ; v1(60.4,37.4) 60.398,37.398 60.398,36.51 59.975,36.086 59.975,35 v1(61.675,33.3) ; v1(73.15,23.675) 72.15,24.675 72.15,26.45 72.977,27.277 72.977,28.602 73.175,28.8 73.175,31.472 72.725,31.922 72.725,34.75 73.25,35.275 v1(73.25,36.625)
  other v1: 72.975,28.3
VMCU_R: R701.1 R702.2 R709.2 TP700.1 U701.1 U701.4 | length 19.6
  Top Layer w0.1: R709.2@30.35,36.2 29.825,35.675 29.825,35 30.125,34.7 30.663,34.7
  Top Layer w0.2: v1(30.258,32.443) 30.273,32.457 30.851,32.457 v1(30.865,32.471) 30.888,32.448 31.352,32.448 U701.4@31.375,32.425 ; U701.1@32.875,32.425 32.887,32.437 33.262,32.437 v1(33.275,32.45)
  Top Layer w0.5: v1(28.9,29.05) 28.902,29.048 29.788,29.048 R702.2@29.816,29.021 ; v1(29.39,33.276) 29.391,33.278 29.935,33.278 v1(29.962,33.302) v1(29.962,33.302) ; v1@29.963,33.304 30.784,34.125 31,34.125 31.175,34.3 31.175,34.35 31.175,34.775 31,34.95 30.663,34.95
  Signal Layer 3 w0.5: v1(28.9,29.05) 28.9,32.787 v1(29.39,33.276) 29.936,33.276 v1(29.962,33.302) ; v1@30,33.25 30.238,33.012 ; v1@30.225,32.45 30.232,32.457 v1@30.244,32.457 ; v1(30.258,32.443) v1@30.244,32.457 ; v1@30.7,32.475 30.7,32.55 30.238,33.012 ; v1@30.85,32.425 30.886,32.461 33.264,32.461 v1(33.275,32.45) ; v1(30.865,32.471) 30.851,32.457 v1@30.244,32.457 ; 30.238,33.012 30.238,32.464 v1@30.244,32.457
  Bottom Layer w0.5: v1(29.39,33.276) 29.391,33.278 29.935,33.278 v1(29.962,33.302) v1(29.962,33.302) 29.962,33.304 29.9,33.366 TP700.1@29.9,34.4
VMCU_S: C700.1 C701.1 R701.2 R710.2 R760.2 TP701.1 TP705.1 U700.3 U702.2 U702.4 U702.9 U702.10 | length 38
  Top Layer w0.1: R701.2@28.325,34.7 29.325,34.7 29.625,35 29.625,35.725 R710.2@29.15,36.2
  Top Layer w0.2: U700.3@24.775,33.925 25.15,33.925 ; 25.3,34.175 25.2,34.075 25.2,33.817 25.317,33.7 25.57,33.7 R760.2@25.573,33.703 ; v1@25.573,34.148 R760.2@25.573,33.703 ; C701.1@26.075,33.725 26.075,33.704 26.074,33.703 R760.2@25.573,33.703 ; C701.1@26.134,33.687 C701.1@26.134,33.69 ; 26.15,34.275 26.134,34.259 26.134,34.225 C701.1@26.134,33.69 ; C700.1@26.9,34.125 26.9,34.118 26.532,33.75 26.194,33.75 C701.1@26.134,33.69 ; U702.10@41.815,36.675 42.5,36.675 v1(42.602,36.777) ; U702.9@41.815,37.075 42.25,37.075 v1@42.475,36.85 ; U702.2@43.585,36.275 43.2,36.275 42.698,36.777 v1(42.602,36.777) ; U702.4@43.585,37.075 43.175,37.075 43,36.9 42.725,36.9 v1(42.602,36.777)
  Top Layer w0.25: U700.3@24.775,33.925 24.75,33.95 U700.3@24.75,34.075 24.75,34.2 24.775,34.225 v1(25.575,34.225)
  Top Layer w0.5: v1@25.504,34.225 26.134,34.225 C700.1@27.033,34.225 C700.1@27.033,34.351 ; v1(25.9,34.725) v1(25.9,34.725) 26.134,34.489 26.134,34.259 ; C700.1@26.968,34.287 C700.1@27.033,34.351 ; 27.075,35.125 27.033,35.083 C700.1@27.033,34.351 ; 27.375,35.2 28.15,35.2 28.325,35.025 R701.2@28.325,34.7 28.325,34.55 28.15,34.375 27.056,34.375 C700.1@27.033,34.351
  Signal Layer 3 w0.6: v1(25.575,34.225) 25.575,34.4 26.835,35.66 ; 26.835,35.661 27.775,36.6 42.425,36.6 v1(42.602,36.777)
  Bottom Layer w0.5: v1(27.771,36.596) 27.772,36.594 27.87,36.594 28.465,36 TP701.1@28.6,36 ; TP705.1@41.6,36.2 42.177,36.777 v1(42.602,36.777)
VMCU_SENSE: C632.1 R630.1 R631.2 TP708.1 U910.6 | length 4.9
  Top Layer w0.1: v1(49.575,34.1) 49.65,34.025 U910.6@50.625,34.025 50.65,34 51.05,34 C632.1@51.05,32.775 51.075,32.8 R631.2@51.6,32.8 R630.1@52.15,32.8
  Bottom Layer w0.1: TP708.1@48.8,34.8 49.5,34.1 v1(49.575,34.1)
VTARGET: R629.2 R691.1 U800.1 U806.1 | length 29.5
  Top Layer w0.3: R691.1@63.477,26.187 63.476,26.186 63.476,26.173 R629.2@64.409,26.173 ; R629.2@64.419,26.163 R629.2@64.409,26.173 ; v1(64.477,26.652) 64.439,26.614 64.439,26.173 R629.2@64.409,26.173 ; U806.1@72.35,34.85 72.45,34.85 72.575,34.975 72.575,35.269 72.518,35.325 v1(72.518,35.382) ; U800.1@72.35,43.85 72.35,44.375 v1(72.475,44.5)
  Signal Layer 3 w0.3: v1(64.477,26.652) 64.519,26.652 64.996,26.175 67.861,26.175 68.226,25.811 70.386,25.811 v1(70.425,25.85)
  Signal Layer 4 w0.3: v1(70.425,25.85) 72.25,27.675 72.25,28.769 72.45,28.969 v1(72.45,29.025) 72.025,29.45 72.025,34.832 72.518,35.325 v1(72.518,35.382) ; v1(72.475,44.5) 73.025,43.95 73.025,40.1 72.593,39.668 72.593,36.421 72.518,36.346 72.518,35.456 v1@72.593,35.382
VTARGET_BUF: C655.1 C806.1 L801.1 R636.2 R687.2 R801.2 R809.2 U808.23 U808.24 | length 80.2
  Top Layer w0.2: v1(63.731,47.322) 63.731,47.274 64.155,46.85 C806.1@64.175,46.85 ; R801.2@67.849,42.793 68.266,42.793 68.523,43.05 v1(68.525,43.05)
  Top Layer w0.3: R687.2@29.656,22.903 29.688,22.935 30.454,22.935 C655.1@30.59,23.071 ; C655.1@30.604,23.036 30.712,22.928 30.712,22.225 v1(30.752,22.186) ; R636.2@47.2,32.8 47.2,33.625 v1(47.35,33.775) ; L801.1@54.7,37.3 L801.1@54.709,37.309 ; R809.2@54.925,38.125 54.925,37.525 L801.1@54.709,37.309 ; v1(55.575,37.312) 55.572,37.309 L801.1@54.709,37.309 ; C806.1@64.15,46.825 U808.24@64.15,45.845 65.005,45.845 65.195,45.655 U808.23@65.195,45.3 ; v1@68.45,43.05 v1@68.523,43.05
  Signal Layer 3 w0.3: v1(30.752,22.186) 47.789,22.186 47.838,22.235 47.985,22.235 v1(48.025,22.275)
  Signal Layer 3 w0.4: v1(47.35,33.775) 47.366,33.791 47.366,34.166 47.85,34.65 53.625,34.65 55.575,36.6 ; v1(60.625,35.45) 57.438,35.45 56.138,36.75 ; 55.575,36.6 v1(55.575,37.312) 56.138,36.75 ; 55.575,36.6 55.759,36.784 56.091,36.784 56.125,36.75 56.138,36.75
  Signal Layer 4 w0.3: v1@47.3,33.725 47.344,33.725 47.39,33.679 47.39,33.079 48.7,31.769 48.7,28.55 48.025,27.875 48.025,22.371 48.046,22.35 v1@48.075,22.35
  Signal Layer 4 w0.4: v1(60.625,35.45) 60.625,35.479 61.175,36.029 61.175,38.275 59.925,39.525 59.925,41.225 60.55,41.85 61.05,41.85 61.7,42.5 61.7,45.29 v1(63.731,47.322) 63.731,47.731 64.525,48.525 66.825,48.525 ; 66.825,48.5 67.287,48.5 67.861,47.926 67.861,46.664 68.375,46.15 68.375,44.434 68.793,44.016 68.793,43.293 v1@68.5,43
VTARGET_SENSE: C638.1 R636.1 R637.2 U910.5 | length 3.2
  Top Layer w0.1: C638.1@46.1,32.775 46.125,32.8 R637.2@46.65,32.8 ; U910.5@46.225,34.025 U910.5@46.65,34.025 ; U910.5@46.775,34.025 U910.5@46.65,34.025 ; R636.1@47.2,32.2 47.2,32.25 R637.2@46.65,32.8 ; R637.2@46.65,32.8 U910.5@46.65,34.025
VTREF: Q800.4 R816.2 TPJ817.1 U800.2 | length 54.2
  Top Layer w0.3: Q800.4@67.325,36.65 67.325,35.725 v1(67.45,35.6) ; U800.2@71.9,44.8 71.9,45.65 72.085,45.835 72.085,46.335 v1(72.125,46.375)
  Signal Layer 3 w0.3: v1(65.689,45.981) 65.729,46.02 66.023,46.02 66.071,46.068 68.507,46.068 68.575,46 71.75,46 v1(72.125,46.375) 72.181,46.375 72.438,46.118 72.537,46.118 72.538,46.117 73.083,46.117 75.325,43.875 98.175,43.875 101.475,47.175 v1(101.475,47.2)
  Signal Layer 4 w0.3: v1(65.689,45.981) 65.689,45.924 65.35,45.585 65.35,40.725 67.175,38.9 67.175,37.825 67.45,37.55 v1(67.45,35.6)
  Bottom Layer w0.5: v1(101.475,47.2) 101.477,47.202 101.502,47.202 TPJ817.1@102.65,48.35
pads on no net: D800.5 D801.1 J101.3 J101.4 M2.1 M3.1 P100.11 P100.12 P101.M1 P101.M2 P601.25@1.8,56.82 P601.26@1.8,48.18 P601.27@6.2,56.525 P601.27@6.85,56.82 P601.28@6.2,48.475 P601.28@6.85,48.18 P601.A2 P601.A3 P601.A8 P601.A10 P601.A11 P601.B2 P601.B3 P601.B8 P601.B10 P601.B11 P601.M1 P601.M2 P800.7 P800.11 P800.13 P801.10 P801.12 P801.14 P801.16 P801.18 P801.20 P801.M1 P801.M2 Q100.3 RP800.2 RP800.7 SW105.7 SW105.8 SW105.M1 SW105.M2 U1.4 U1.5 U600.8 U701.8 U800.17 U802.17 U806.17 U808.8 U808.9 U808.10 U810.17 U900.B11 U900.E12 U900.F12 U900.G2 U900.H2 U900.J2 U900.L3 U900.L8 U900.L12 U900.M4 U900.M12 U900.M13 U900.N7 U900.N12 U901.9 U902.C1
